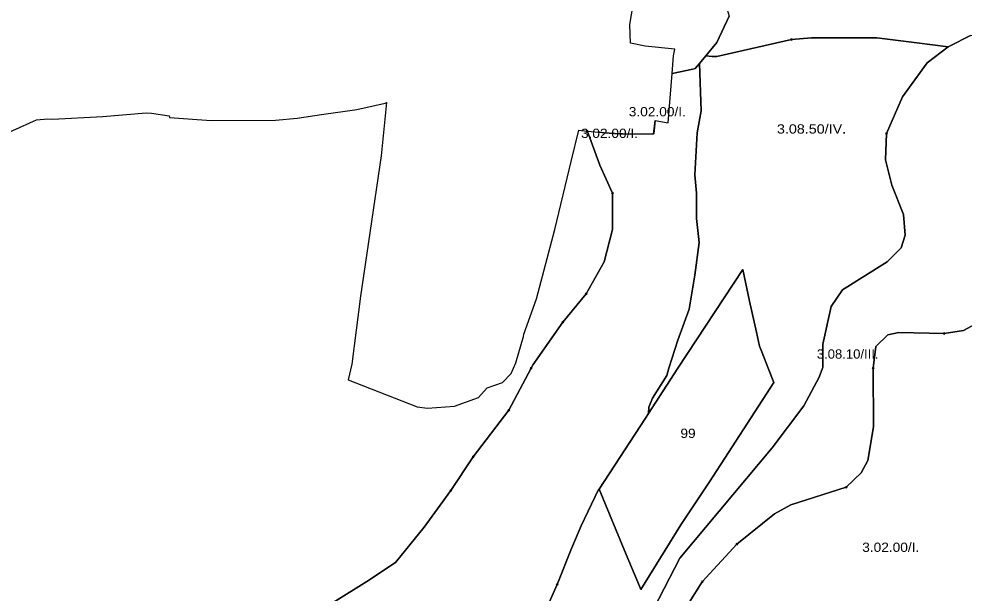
# Model space of a CAD drawing. Extents: x -650455 to -642254, y -1075222 to -1066610.
# Drawn here: x -646541 to -645525, y -1068242 to -1067624 of the extents above; entities that cross this region are included whole.
import ezdxf
from ezdxf.enums import TextEntityAlignment as Align

# ---------------------------------------------------------------- set-up
doc = ezdxf.new("R2010")
doc.units = 0
doc.header["$LTSCALE"] = 4
doc.header["$PDMODE"] = 32
doc.header["$PDSIZE"] = 2
for name, color, linetype, lineweight in [('1', 7, 'Continuous', 25), ('11', 7, 'Continuous', 13), ('12', 7, 'Continuous', 13), ('13', 7, 'Continuous', 13), ('14', 7, 'Continuous', 13), ('16', 7, 'Continuous', 13)]:
    doc.layers.add(name, color=color, linetype=linetype, lineweight=lineweight)
doc.layers.add('2', color=7, linetype='Continuous')

msp = doc.modelspace()

# ---------------------------------------------------------------- linework, layer by layer
at = {"layer": '1'}
for points in [[(-645802.687, -1067663.876), (-645809.375, -1067672.25), (-645814.125, -1067677.751), (-645816.835, -1067678.312), (-645839.087, -1067682.923), (-645837.619, -1067663.994), (-645836.027, -1067656.984), (-645867.933, -1067653.635), (-645883.859, -1067650.419), (-645884.5, -1067630.76), (-645873.323, -1067563.051), (-645890.073, -1067549.417), (-645890.669, -1067543.411), (-645885.177, -1067516.651), (-645845.49, -1067511.661), (-645830.352, -1067509.283), (-645829.312, -1067510.75), (-645814.25, -1067527.251), (-645796.188, -1067560.375), (-645788.625, -1067583), (-645788.254, -1067585.104), (-645788.25, -1067585.125), (-645777.5, -1067621.251), (-645790.813, -1067649.501)], [(-645857.007, -1067733.671), (-645858.438, -1067747.75), (-645858.794, -1067747.75), (-645857.238, -1067733.631)], [(-645892.381, -1067747.75), (-645895.062, -1067747.75), (-645912.313, -1067746.751), (-645917.164, -1067746.206)], [(-645917.313, -1068130.126), (-645867.687, -1068053.501), (-645864.5, -1068048.626), (-645832.678, -1068000), (-645763.063, -1067893.626), (-645755.688, -1067927.876), (-645748.438, -1067961.001), (-645744.938, -1067976.25), (-645742.687, -1067982.125), (-645735.605, -1068000), (-645729.568, -1068015.238), (-645729.57, -1068015.25), (-645798.69, -1068122.171), (-645829.66, -1068168.341), (-645867.779, -1068230.191), (-645872.671, -1068238), (-645874.15, -1068234.441), (-645882.74, -1068213.72), (-645888.25, -1068200.251)]]:
    msp.add_lwpolyline(points, close=True, dxfattribs=at)
for points in [[(-645466.563, -1067650.126), (-645518.5, -1067642.001), (-645541, -1067653.501), (-645542.25, -1067654.375), (-645576, -1067649.875), (-645619.125, -1067644.625), (-645689.063, -1067644.625), (-645710.625, -1067646.5), (-645790.875, -1067664.75), (-645796.062, -1067664.75), (-645802.687, -1067663.876), (-645790.813, -1067649.501), (-645777.5, -1067621.251)], [(-645864.5, -1068269.501), (-645830.5, -1068204.001), (-645731.5, -1068085.5), (-645697.5, -1068040.5), (-645681, -1068009.501), (-645677.381, -1068000), (-645677, -1067999), (-645677, -1067974.001), (-645668, -1067933.501), (-645656, -1067915.5), (-645608, -1067885.5), (-645593, -1067870.5), (-645588.5, -1067857.001), (-645590.5, -1067834.5), (-645603, -1067803.001), (-645609.5, -1067776.001), (-645608.5, -1067747.501), (-645591.5, -1067708), (-645565, -1067671.5), (-645542.25, -1067654.375), (-645541, -1067653.501), (-645518.5, -1067642.001)], [(-645814.437, -1067791.875), (-645812.125, -1067746.751), (-645807.625, -1067723.125), (-645809.375, -1067672.25), (-645802.687, -1067663.876), (-645796.062, -1067664.75), (-645790.875, -1067664.75), (-645710.625, -1067646.5), (-645689.063, -1067644.625), (-645619.125, -1067644.625), (-645576, -1067649.875), (-645542.25, -1067654.375)], [(-645542.25, -1067654.375), (-645565, -1067671.5), (-645591.5, -1067708), (-645608.5, -1067747.501), (-645609.5, -1067776.001), (-645603, -1067803.001), (-645590.5, -1067834.5), (-645588.5, -1067857.001), (-645593, -1067870.5), (-645608, -1067885.5), (-645656, -1067915.5), (-645668, -1067933.501), (-645677, -1067974.001), (-645677, -1067999), (-645677.381, -1068000), (-645681, -1068009.501), (-645697.5, -1068040.5), (-645731.5, -1068085.5), (-645830.5, -1068204.001), (-645864.5, -1068269.501)], [(-645858.438, -1067747.75), (-645857.007, -1067733.671), (-645843.207, -1067736.051), (-645839.087, -1067682.923), (-645816.835, -1067678.312), (-645814.125, -1067677.751), (-645809.375, -1067672.25), (-645807.625, -1067723.125), (-645812.125, -1067746.751), (-645814.437, -1067791.875), (-645812.938, -1067811.625), (-645812.938, -1067839.001), (-645809.875, -1067864.875), (-645814.437, -1067899.875), (-645820.5, -1067936.251), (-645832.688, -1067969.751), (-645842.34, -1068000), (-645844.812, -1068007.75), (-645860, -1068032), (-645863.813, -1068041.625), (-645864.5, -1068048.626)], [(-646334.1, -1067733.4), (-646265.3, -1067733), (-646241.8, -1067731.001), (-646215.6, -1067727.001), (-646177.7, -1067721.601), (-646147.4, -1067714.8), (-646145.864, -1067714.305), (-646151.5, -1067771.46), (-646173.854, -1067922.41), (-646183.168, -1067995.4), (-646186.894, -1068012.483), (-646113.002, -1068041.368), (-646101.826, -1068042.921), (-646072.642, -1068040.746), (-646047.184, -1068031.428), (-646037.588, -1068021.117), (-646021.3, -1068015.101), (-646011.9, -1068005.551), (-646007, -1067994.3), (-645998.8, -1067965.701), (-645998.424, -1067963.832), (-645998.13, -1067963.409), (-645984.78, -1067925.205), (-645964.91, -1067850.661), (-645947.524, -1067777.671), (-645939.12, -1067744.039), (-645930.106, -1067744.937), (-645930.062, -1067745.376), (-645916.5, -1067781.5), (-645902.938, -1067811.625), (-645902.938, -1067850.75), (-645912, -1067885.375), (-645931.312, -1067920.001), (-645956.375, -1067950.25), (-645988.312, -1067995.75), (-645990.562, -1068000), (-646014.375, -1068045), (-646052.625, -1068095.375), (-646076.688, -1068131.501), (-646105.312, -1068170.75)], [(-646573.28, -1067755.921), (-646522.089, -1067732.688), (-646509.898, -1067731.813), (-646504.716, -1067732.104), (-646450.811, -1067729.365), (-646404.167, -1067725.184), (-646398.3, -1067725.601), (-646379.3, -1067728.5), (-646379.05, -1067730.4), (-646334.1, -1067733.4)], [(-646203.125, -1068252.001), (-646167, -1068229.375), (-646136.312, -1068209.001), (-646105.312, -1068170.75), (-646076.688, -1068131.501), (-646052.625, -1068095.375), (-646014.375, -1068045), (-645990.562, -1068000), (-645988.312, -1067995.75), (-645956.375, -1067950.25), (-645931.312, -1067920.001), (-645912, -1067885.375), (-645902.938, -1067850.75), (-645902.938, -1067811.625), (-645916.5, -1067781.5), (-645930.062, -1067745.376), (-645930.106, -1067744.937), (-645917.73, -1067746.171), (-645917.164, -1067746.206), (-645912.313, -1067746.751), (-645895.062, -1067747.75), (-645892.381, -1067747.75), (-645892.22, -1067747.761), (-645858.82, -1067747.99), (-645858.794, -1067747.75), (-645858.438, -1067747.75)], [(-645977.937, -1068267.25), (-645962.438, -1068232.625), (-645947.25, -1068193.626), (-645936.625, -1068169.376), (-645918.062, -1068130.501), (-645917.313, -1068130.126), (-645888.25, -1068200.251), (-645882.74, -1068213.72), (-645874.15, -1068234.441), (-645872.671, -1068238), (-645867.779, -1068230.191), (-645829.66, -1068168.341), (-645798.69, -1068122.171), (-645729.57, -1068015.25), (-645729.568, -1068015.238), (-645735.605, -1068000), (-645742.687, -1067982.125), (-645744.938, -1067976.25), (-645748.438, -1067961.001), (-645755.688, -1067927.876), (-645763.063, -1067893.626), (-645832.678, -1068000), (-645864.5, -1068048.626), (-645863.813, -1068041.625), (-645860, -1068032), (-645844.812, -1068007.75), (-645842.34, -1068000), (-645832.688, -1067969.751), (-645820.5, -1067936.251), (-645814.437, -1067899.875), (-645809.875, -1067864.875), (-645812.938, -1067839.001), (-645812.938, -1067811.625), (-645814.437, -1067791.875)], [(-645508.5, -1067950.001), (-645526, -1067959.5), (-645546.5, -1067962.5), (-645595.5, -1067961.501), (-645607, -1067964), (-645620, -1067976.5), (-645623, -1068000), (-645622.5, -1068063.001), (-645628.5, -1068099.001), (-645636, -1068112.5), (-645652, -1068128.001), (-645711.5, -1068147.001), (-645729, -1068156.501), (-645769.5, -1068189.001), (-645806.5, -1068229.501), (-645820.5, -1068252.001), (-645833, -1068292.501), (-645837, -1068328.5), (-645828.5, -1068378.001), (-645800.5, -1068459.001), (-645791.5, -1068490.5), (-645783, -1068502.5), (-645817, -1068530), (-645835.5, -1068533.001)], [(-645820.5, -1068252.001), (-645806.5, -1068229.501), (-645769.5, -1068189.001), (-645729, -1068156.501), (-645711.5, -1068147.001), (-645652, -1068128.001), (-645636, -1068112.5), (-645628.5, -1068099.001), (-645622.5, -1068063.001), (-645623, -1068000), (-645620, -1067976.5), (-645607, -1067964), (-645595.5, -1067961.501), (-645546.5, -1067962.5), (-645526, -1067959.5), (-645508.5, -1067950.001)], [(-645864.5, -1068048.626), (-645867.687, -1068053.501), (-645917.313, -1068130.126), (-645918.062, -1068130.501), (-645936.625, -1068169.376), (-645947.25, -1068193.626), (-645962.438, -1068232.625), (-645977.937, -1068267.25)], [(-646105.312, -1068170.75), (-646136.312, -1068209.001), (-646167, -1068229.375), (-646203.125, -1068252.001)]]:
    msp.add_lwpolyline(points, dxfattribs=at)
at = {"layer": '11'}
for p, q in [((-646014.375, -1068045), (-645990.562, -1068000)), ((-646052.625, -1068095.375), (-646014.375, -1068045))]:
    msp.add_line(p, q, dxfattribs=at)
for points in [[(-645884.5, -1067630.76), (-645883.859, -1067650.419), (-645867.933, -1067653.635), (-645836.027, -1067656.984), (-645837.619, -1067663.994), (-645839.087, -1067682.923), (-645816.835, -1067678.312), (-645814.125, -1067677.751), (-645809.375, -1067672.25), (-645802.687, -1067663.876), (-645790.813, -1067649.501), (-645777.5, -1067621.251), (-645788.25, -1067585.125), (-645788.254, -1067585.104), (-645788.625, -1067583), (-645796.188, -1067560.375), (-645814.25, -1067527.251), (-645829.312, -1067510.75), (-645830.352, -1067509.283), (-645845.49, -1067511.661), (-645885.177, -1067516.651), (-645890.669, -1067543.411), (-645890.073, -1067549.417), (-645873.323, -1067563.051)], [(-645858.794, -1067747.75), (-645858.438, -1067747.75), (-645857.007, -1067733.671), (-645857.238, -1067733.631)], [(-645895.062, -1067747.75), (-645892.381, -1067747.75), (-645917.164, -1067746.206), (-645912.313, -1067746.751)]]:
    msp.add_lwpolyline(points, close=True, dxfattribs=at)
for points in [[(-645931.312, -1067920.001), (-645912, -1067885.375), (-645902.938, -1067850.75), (-645902.938, -1067811.625), (-645916.5, -1067781.5), (-645930.062, -1067745.376), (-645930.106, -1067744.937), (-645939.12, -1067744.039), (-645947.524, -1067777.671), (-645964.91, -1067850.661), (-645984.78, -1067925.205), (-645998.13, -1067963.409), (-645998.424, -1067963.832), (-645998.8, -1067965.701), (-646007, -1067994.3), (-646011.9, -1068005.551), (-646021.3, -1068015.101), (-646037.588, -1068021.117), (-646047.184, -1068031.428), (-646072.642, -1068040.746), (-646101.826, -1068042.921), (-646113.002, -1068041.368), (-646186.894, -1068012.483), (-646183.168, -1067995.4), (-646173.854, -1067922.41), (-646151.5, -1067771.46), (-646145.864, -1067714.305), (-646147.4, -1067714.8), (-646177.7, -1067721.601), (-646215.6, -1067727.001), (-646241.8, -1067731.001), (-646265.3, -1067733), (-646334.1, -1067733.4), (-646379.05, -1067730.4), (-646379.3, -1067728.5), (-646398.3, -1067725.601), (-646404.167, -1067725.184), (-646450.811, -1067729.365), (-646504.716, -1067732.104), (-646509.898, -1067731.813)], [(-646509.898, -1067731.813), (-646522.089, -1067732.688), (-646573.28, -1067755.921)], [(-645487.5, -1067912.501), (-645494.5, -1067932), (-645508.5, -1067950.001), (-645526, -1067959.5), (-645546.5, -1067962.5)], [(-645990.562, -1068000), (-645988.312, -1067995.75), (-645956.375, -1067950.25), (-645931.312, -1067920.001)], [(-645546.5, -1067962.5), (-645595.5, -1067961.501), (-645607, -1067964), (-645620, -1067976.5), (-645623, -1068000)], [(-645623, -1068000), (-645622.5, -1068063.001), (-645628.5, -1068099.001), (-645636, -1068112.5), (-645652, -1068128.001)], [(-646268.75, -1068288.751), (-646239.25, -1068276.126), (-646203.125, -1068252.001), (-646167, -1068229.375), (-646136.312, -1068209.001), (-646105.312, -1068170.75), (-646076.688, -1068131.501), (-646052.625, -1068095.375)], [(-645652, -1068128.001), (-645711.5, -1068147.001), (-645729, -1068156.501), (-645769.5, -1068189.001), (-645806.5, -1068229.501)], [(-645806.5, -1068229.501), (-645820.5, -1068252.001), (-645833, -1068292.501), (-645837, -1068328.5), (-645828.5, -1068378.001)]]:
    msp.add_lwpolyline(points, dxfattribs=at)
for p in [(-645931.312, -1067920.001), (-645546.5, -1067962.5), (-645990.562, -1068000), (-645623, -1068000), (-646014.375, -1068045), (-646052.625, -1068095.375), (-645652, -1068128.001), (-645806.5, -1068229.501)]:
    msp.add_point(p, dxfattribs=at)
at = {"layer": '12'}
msp.add_line((-645977.937, -1068267.25), (-645962.438, -1068232.625), dxfattribs=at)
for points in [[(-645755.688, -1067444.626), (-645751.066, -1067481.89), (-645749.67, -1067492.54), (-645786.52, -1067502.401), (-645830.352, -1067509.283), (-645829.312, -1067510.75), (-645814.25, -1067527.251), (-645796.188, -1067560.375), (-645788.625, -1067583), (-645788.254, -1067585.104), (-645788.25, -1067585.125), (-645777.5, -1067621.251), (-645790.813, -1067649.501), (-645802.687, -1067663.876), (-645796.062, -1067664.75), (-645790.875, -1067664.75), (-645710.625, -1067646.5)], [(-645710.625, -1067646.5), (-645689.063, -1067644.625), (-645619.125, -1067644.625), (-645576, -1067649.875), (-645542.25, -1067654.375), (-645541, -1067653.501), (-645518.5, -1067642.001), (-645466.563, -1067650.126), (-645436.375, -1067646.251), (-645421.375, -1067644.751), (-645413.813, -1067638.626), (-645409.312, -1067620.625)], [(-645962.438, -1068232.625), (-645947.25, -1068193.626), (-645936.625, -1068169.376), (-645918.062, -1068130.501), (-645917.313, -1068130.126), (-645867.687, -1068053.501), (-645864.5, -1068048.626), (-645863.813, -1068041.625), (-645860, -1068032), (-645844.812, -1068007.75), (-645842.34, -1068000), (-645832.688, -1067969.751), (-645820.5, -1067936.251), (-645814.437, -1067899.875), (-645809.875, -1067864.875), (-645812.938, -1067839.001), (-645812.938, -1067811.625), (-645814.437, -1067791.875), (-645812.125, -1067746.751), (-645807.625, -1067723.125), (-645809.375, -1067672.25), (-645814.125, -1067677.751), (-645816.835, -1067678.312), (-645839.087, -1067682.923), (-645843.207, -1067736.051), (-645857.007, -1067733.671), (-645858.438, -1067747.75), (-645858.794, -1067747.75), (-645858.82, -1067747.99), (-645892.22, -1067747.761), (-645892.381, -1067747.75), (-645895.062, -1067747.75), (-645912.313, -1067746.751), (-645917.164, -1067746.206), (-645917.73, -1067746.171), (-645930.106, -1067744.937)], [(-645930.106, -1067744.937), (-645930.062, -1067745.376), (-645916.5, -1067781.5), (-645902.938, -1067811.625)], [(-645902.938, -1067811.625), (-645902.938, -1067850.75), (-645912, -1067885.375), (-645931.312, -1067920.001), (-645956.375, -1067950.25)], [(-645956.375, -1067950.25), (-645988.312, -1067995.75), (-645990.562, -1068000), (-646014.375, -1068045)], [(-646014.375, -1068045), (-646052.625, -1068095.375), (-646076.688, -1068131.501)], [(-646076.688, -1068131.501), (-646105.312, -1068170.75), (-646136.312, -1068209.001), (-646167, -1068229.375), (-646203.125, -1068252.001)]]:
    msp.add_lwpolyline(points, dxfattribs=at)
for p in [(-645710.625, -1067646.5), (-645930.106, -1067744.937), (-645902.938, -1067811.625), (-645956.375, -1067950.25), (-646014.375, -1068045), (-646076.688, -1068131.501), (-645962.438, -1068232.625)]:
    msp.add_point(p, dxfattribs=at)
at = {"layer": '13'}
for points in [[(-645518.5, -1067642.001), (-645541, -1067653.501), (-645542.25, -1067654.375), (-645565, -1067671.5), (-645591.5, -1067708), (-645608.5, -1067747.501), (-645609.5, -1067776.001), (-645603, -1067803.001), (-645590.5, -1067834.5), (-645588.5, -1067857.001)], [(-645588.5, -1067857.001), (-645593, -1067870.5), (-645608, -1067885.5), (-645656, -1067915.5), (-645668, -1067933.501), (-645677, -1067974.001)], [(-645769.5, -1068189.001), (-645729, -1068156.501), (-645711.5, -1068147.001), (-645652, -1068128.001), (-645636, -1068112.5), (-645628.5, -1068099.001), (-645622.5, -1068063.001), (-645623, -1068000), (-645620, -1067976.5), (-645607, -1067964), (-645595.5, -1067961.501), (-645546.5, -1067962.5), (-645526, -1067959.5), (-645508.5, -1067950.001)], [(-645677, -1067974.001), (-645677, -1067999), (-645677.381, -1068000), (-645681, -1068009.501), (-645697.5, -1068040.5), (-645731.5, -1068085.5), (-645830.5, -1068204.001), (-645864.5, -1068269.501), (-645883, -1068323.5), (-645887, -1068364), (-645883, -1068395.001), (-645873, -1068422.501), (-645858, -1068454), (-645844, -1068521.5)], [(-645791.5, -1068490.5), (-645800.5, -1068459.001), (-645828.5, -1068378.001), (-645837, -1068328.5), (-645833, -1068292.501), (-645820.5, -1068252.001), (-645806.5, -1068229.501), (-645769.5, -1068189.001)]]:
    msp.add_lwpolyline(points, dxfattribs=at)
msp.add_point((-645769.5, -1068189.001), dxfattribs=at)
at = {"layer": '14'}
for points in [[(-645608.5, -1067747.501), (-645591.5, -1067708), (-645565, -1067671.5), (-645542.25, -1067654.375), (-645576, -1067649.875), (-645619.125, -1067644.625), (-645689.063, -1067644.625), (-645710.625, -1067646.5), (-645790.875, -1067664.75), (-645796.062, -1067664.75), (-645802.687, -1067663.876), (-645809.375, -1067672.25), (-645807.625, -1067723.125), (-645812.125, -1067746.751), (-645814.437, -1067791.875), (-645812.938, -1067811.625), (-645812.938, -1067839.001), (-645809.875, -1067864.875), (-645814.437, -1067899.875), (-645820.5, -1067936.251), (-645832.688, -1067969.751), (-645842.34, -1068000), (-645844.812, -1068007.75), (-645860, -1068032), (-645863.813, -1068041.625), (-645864.5, -1068048.626), (-645832.678, -1068000), (-645763.063, -1067893.626), (-645755.688, -1067927.876), (-645748.438, -1067961.001), (-645744.938, -1067976.25), (-645742.687, -1067982.125), (-645735.605, -1068000)], [(-645873, -1068422.501), (-645883, -1068395.001), (-645887, -1068364), (-645883, -1068323.5), (-645864.5, -1068269.501), (-645830.5, -1068204.001), (-645731.5, -1068085.5), (-645697.5, -1068040.5), (-645681, -1068009.501), (-645677.381, -1068000), (-645677, -1067999), (-645677, -1067974.001), (-645668, -1067933.501), (-645656, -1067915.5), (-645608, -1067885.5), (-645593, -1067870.5), (-645588.5, -1067857.001), (-645590.5, -1067834.5), (-645603, -1067803.001), (-645609.5, -1067776.001), (-645608.5, -1067747.501)], [(-645735.605, -1068000), (-645729.568, -1068015.238), (-645729.57, -1068015.25), (-645798.69, -1068122.171), (-645829.66, -1068168.341), (-645867.779, -1068230.191), (-645872.671, -1068238), (-645874.15, -1068234.441), (-645882.74, -1068213.72), (-645888.25, -1068200.251), (-645917.313, -1068130.126), (-645918.062, -1068130.501), (-645936.625, -1068169.376), (-645947.25, -1068193.626), (-645962.438, -1068232.625), (-645977.937, -1068267.25), (-645985.875, -1068285.501), (-645985.9, -1068285.558), (-645993.125, -1068302.125), (-646002.938, -1068334.001), (-646001.687, -1068364.75), (-645989.375, -1068400.25), (-645977.063, -1068439.625)]]:
    msp.add_lwpolyline(points, dxfattribs=at)
msp.add_point((-645608.5, -1067747.501), dxfattribs=at)
at = {"layer": '16'}
msp.add_lwpolyline([(-645888.25, -1068200.251), (-645882.74, -1068213.72), (-645874.15, -1068234.441), (-645872.671, -1068238), (-645867.779, -1068230.191), (-645829.66, -1068168.341), (-645798.69, -1068122.171), (-645729.57, -1068015.25), (-645729.568, -1068015.238), (-645735.605, -1068000), (-645742.687, -1067982.125), (-645744.938, -1067976.25), (-645748.438, -1067961.001), (-645755.688, -1067927.876), (-645763.063, -1067893.626), (-645832.678, -1068000), (-645864.5, -1068048.626), (-645867.687, -1068053.501), (-645917.313, -1068130.126)], close=True, dxfattribs=at)

# ---------------------------------------------------------------- texts
at = {"layer": '2'}
for s, width, p in [('3.02.00/I.', 1.1, (-645854.845, -1067729.045)), ('3.02.00/I.', 1.1, (-645906.285, -1067752.331)), ('3.08.50/IV.', 1.15, (-645689.144, -1067747.618)), ('3.08.10/III.', 1.05, (-645650.302, -1067989.624)), ('99', 1.1, (-645821.872, -1068074.921)), ('3.02.00/I.', 1.1, (-645604.029, -1068197.454))]:
    msp.add_text(s, height=10, dxfattribs=dict(at, width=width)).set_placement(p, align=Align.CENTER)

doc.saveas('drawing.dxf')
